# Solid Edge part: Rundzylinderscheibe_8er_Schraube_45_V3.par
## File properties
Author: technik
Template: iso part.par
Last saved by: fknapp
Revision: 31
Application: Solid Edge
Username: hStrempfl
Genauigkeit: 0,990
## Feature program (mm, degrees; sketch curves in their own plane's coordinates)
sketch for "Bohrung_15" plane through (10, 5.8207, 6.3207) normal (0, -0.707107, 0.707107) x-axis (-1, 0, 0)
hole "Bohrung_15" diameter 8 finite
pattern "unnamed Pattern 1" of "Bohrung_15"
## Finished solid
Body 1: solid body, 6 faces, 9 edges, 4 vertices.
  Faces by surface: plane 3, cylinder 2, cone 1
  Edges by curve: circle 4, ellipse 2, line 2, intersection 1
Bounding box of the edges (mm): 20.000 x 20.000 x 9.500, from (0, 0, 0) to (20, 20, 9.5).
Cylindrical faces by radius (mm): R4 x1, R10 x1
Conical faces (half-angle, radius in mm at the cone's reference point): 45 deg R7.5 x1
Planar faces by outward normal: +z 1, -z 1, oblique 1
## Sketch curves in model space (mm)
line (10, 11.5, 12) -> (10, 5.631, 6.131)
line (0, 12.1244, 7.5) -> (0, 12.1244, 0)
line (0, 0, 0) -> (0, 20, 0)
line (0, 20, 0) -> (0, 20, 8)
line (0, 20, 8) -> (0, 0, 8)
line (0, 0, 8) -> (0, 0, 0)
line (0, 0, 0.5) -> (0, 12.1244, 0.5)
line (0, 0, 0) -> (0, 0, 0.5)
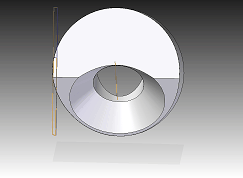
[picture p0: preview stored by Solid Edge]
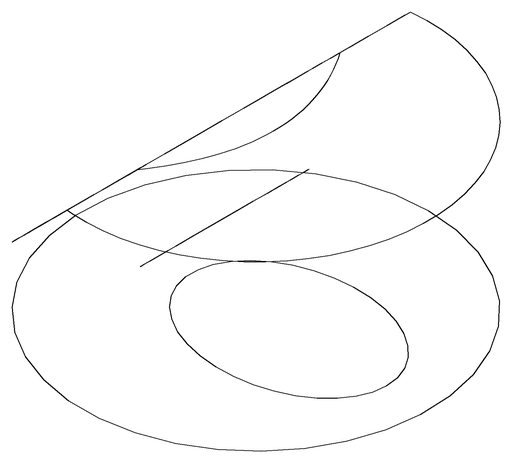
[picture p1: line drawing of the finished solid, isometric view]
